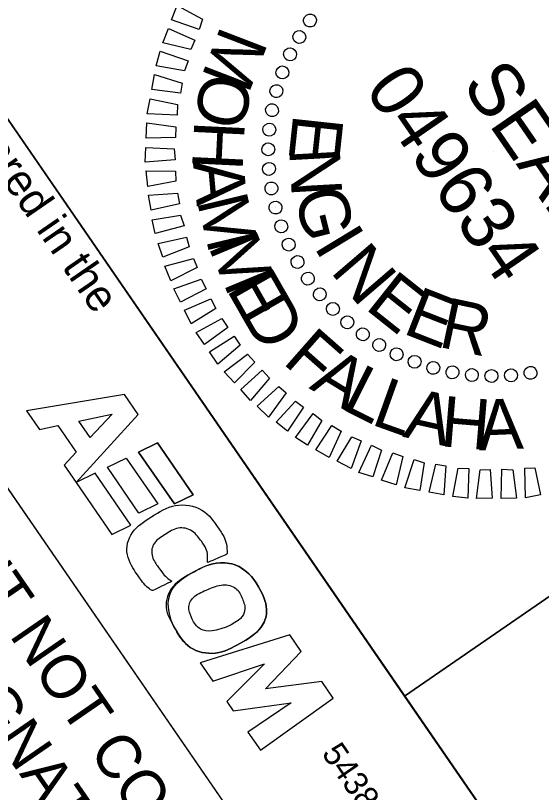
# Model space of a CAD drawing. Extents: x 2297526 to 2298642, y 599613 to 600819.
# Drawn here: x 2298486.8 to 2298526.4, y 599978.2 to 600036.6 of the extents above; entities that cross this region are included whole.
import ezdxf

# ---------------------------------------------------------------- set-up
doc = ezdxf.new("R2010")
doc.units = 0
for name, color, linetype in [('Default', 7, 'Continuous'), ('Exist DTM Drainline Cogo Elevation', 7, 'Continuous'), ('Exist Roads Curbs Cogo Comment', 7, 'Continuous'), ('Exist Roads EOP Cogo Elevation', 7, 'Continuous'), ('Exist Roads EOP Other Cogo Point CELL', 7, 'Continuous'), ('Exist Roads Soil Cogo Point CELL', 7, 'Continuous')]:
    doc.layers.add(name, color=color, linetype=linetype)

# ---------------------------------------------------------------- blocks, each defined once
blk = doc.blocks.new('block 3')
at = {"layer": 'Default'}
blk.add_open_spline([(0.122754, 0.093928), (0.12554, 0.09373), (0.127264, 0.091462), (0.126953, 0.088431), (0.126631, 0.085307), (0.12411, 0.082981), (0.121267, 0.083184), (0.118481, 0.083381), (0.116757, 0.085649), (0.117069, 0.088681), (0.11739, 0.091805), (0.119911, 0.094131), (0.122754, 0.093928)], degree=3, dxfattribs=at)
blk = doc.blocks.new('block 2')
at = {"layer": 'Default'}
for p, q in [((0.102337, 0.09375), (0.101973, 0.091327)), ((0.109658, 0.09375), (0.102337, 0.09375)), ((0.109295, 0.091327), (0.109658, 0.09375)), ((0.101973, 0.091327), (0.109295, 0.091327)), ((0.101374, 0.08733), (0.101738, 0.089754)), ((0.101738, 0.089754), (0.108181, 0.089754)), ((0.108181, 0.089754), (0.107817, 0.08733)), ((0.107817, 0.08733), (0.101374, 0.08733)), ((0.101138, 0.085757), (0.100775, 0.083333)), ((0.10846, 0.085757), (0.101138, 0.085757)), ((0.108096, 0.083333), (0.10846, 0.085757)), ((0.100775, 0.083333), (0.108096, 0.083333))]:
    blk.add_line(p, q, dxfattribs=at)
for points in [[(0.109295, 0.091327), (0.101973, 0.091327), (0.102337, 0.09375), (0.109658, 0.09375), (0.109295, 0.091327)], [(0.107817, 0.08733), (0.101374, 0.08733), (0.101738, 0.089754), (0.108181, 0.089754), (0.107817, 0.08733)], [(0.10846, 0.085757), (0.101138, 0.085757), (0.100775, 0.083333), (0.108096, 0.083333), (0.10846, 0.085757)]]:
    blk.add_lwpolyline(points, dxfattribs=at)
blk = doc.blocks.new('POINT_DISPLAY')
at = {"layer": 'Default'}
blk.add_line((0, 0), (0, 0), dxfattribs=at)

msp = doc.modelspace()

# ---------------------------------------------------------------- linework, layer by layer
at = {"layer": 'Exist DTM Drainline Cogo Elevation'}
for points in [[(2298537.65, 600073.144), (2298571.698, 600023.704), (2298516.106, 599985.419), (2298482.058, 600034.859)], [(2298571.698, 600023.704), (2298605.73, 599974.288), (2298550.137, 599936.003), (2298516.106, 599985.419)]]:
    msp.add_lwpolyline(points, close=True, dxfattribs=at)
at = {"layer": 'Exist Roads Curbs Cogo Comment'}
msp.add_line((2298469.087, 600025.926), (2298537.162, 599927.076), dxfattribs=at)
at = {"layer": 'Exist Roads EOP Cogo Elevation'}
for p, q in [((2298495.008, 600008.108), (2298487.648, 600006.895)), ((2298496.046, 600006.602), (2298495.008, 600008.108)), ((2298487.648, 600006.895), (2298488.611, 600005.496)), ((2298491.371, 600001.489), (2298496.046, 600006.602)), ((2298491.585, 600006.12), (2298494.069, 600006.641)), ((2298494.078, 600006.628), (2298492.431, 600004.891)), ((2298494.069, 600006.641), (2298494.078, 600006.628)), ((2298488.611, 600005.496), (2298490.007, 600005.789)), ((2298490.007, 600005.789), (2298491.385, 600003.787)), ((2298492.431, 600004.891), (2298491.585, 600006.12)), ((2298491.385, 600003.787), (2298490.46, 600002.811)), ((2298490.46, 600002.811), (2298491.371, 600001.489)), ((2298507.457, 599990.033), (2298500.707, 599987.932)), ((2298508.319, 599988.781), (2298507.457, 599990.033)), ((2298505.629, 599985.974), (2298508.319, 599988.781)), ((2298500.707, 599987.932), (2298501.659, 599986.55)), ((2298501.659, 599986.55), (2298505.561, 599987.852)), ((2298505.561, 599987.852), (2298502.713, 599985.019)), ((2298509.87, 599986.529), (2298505.629, 599985.974)), ((2298510.733, 599985.275), (2298509.87, 599986.529)), ((2298505.244, 599981.345), (2298510.733, 599985.275)), ((2298502.713, 599985.019), (2298503.198, 599984.315)), ((2298503.198, 599984.315), (2298507.573, 599984.927)), ((2298507.573, 599984.927), (2298504.307, 599982.706)), ((2298504.307, 599982.706), (2298505.244, 599981.345))]:
    msp.add_line(p, q, dxfattribs=at)
for points in [[(2298490.46, 600002.811), (2298491.371, 600001.489), (2298496.046, 600006.602), (2298495.008, 600008.108), (2298487.648, 600006.895), (2298488.611, 600005.496), (2298490.007, 600005.789), (2298491.385, 600003.787), (2298490.46, 600002.811)], [(2298505.244, 599981.345), (2298510.733, 599985.275), (2298509.87, 599986.529), (2298505.629, 599985.974), (2298508.319, 599988.781), (2298507.457, 599990.033), (2298500.707, 599987.932), (2298501.659, 599986.55), (2298505.561, 599987.852), (2298502.713, 599985.019), (2298503.198, 599984.315), (2298507.573, 599984.927), (2298504.307, 599982.706), (2298505.244, 599981.345)]]:
    msp.add_lwpolyline(points, dxfattribs=at)
for points in [[(2298498.586, 599994.064), (2298498.157, 599994.318), (2298497.746, 599994.855), (2298497.558, 599995.128), (2298496.952, 599996.007), (2298497.151, 599997.003), (2298498.063, 599997.588), (2298499.027, 599998.205), (2298500.192, 599997.958), (2298500.858, 599996.991), (2298501.173, 599996.534), (2298501.299, 599996.028), (2298501.243, 599995.457), (2298501.243, 599995.457), (2298502.758, 599996.106), (2298502.758, 599996.106), (2298502.703, 599996.882), (2298502.517, 599997.437), (2298502.119, 599998.016), (2298501.016, 599999.617), (2298498.773, 600000.019), (2298497.059, 599998.921), (2298495.397, 599997.856), (2298494.982, 599996.013), (2298496.063, 599994.443), (2298496.251, 599994.171), (2298496.686, 599993.6), (2298497.114, 599993.346), (2298497.114, 599993.346), (2298498.586, 599994.064), (2298498.586, 599994.064)], [(2298498.586, 599994.064), (2298498.157, 599994.318), (2298497.746, 599994.855), (2298497.558, 599995.128), (2298496.952, 599996.007), (2298497.151, 599997.003), (2298498.063, 599997.588), (2298499.027, 599998.205), (2298500.192, 599997.958), (2298500.858, 599996.991), (2298501.173, 599996.534), (2298501.299, 599996.028), (2298501.243, 599995.457), (2298501.243, 599995.457), (2298502.758, 599996.106), (2298502.758, 599996.106), (2298502.703, 599996.882), (2298502.517, 599997.437), (2298502.119, 599998.016), (2298501.016, 599999.617), (2298498.773, 600000.019), (2298497.059, 599998.921), (2298495.397, 599997.856), (2298494.982, 599996.013), (2298496.063, 599994.443), (2298496.251, 599994.171), (2298496.686, 599993.6), (2298497.114, 599993.346), (2298497.114, 599993.346), (2298498.586, 599994.064), (2298498.586, 599994.064)], [(2298498.528, 599991.147), (2298498.084, 599992.523), (2298498.718, 599993.941), (2298500.213, 599994.759), (2298501.998, 599995.736), (2298504.166, 599995.245), (2298505.103, 599993.653)], [(2298505.103, 599993.653), (2298506.022, 599992.093), (2298505.445, 599990.34), (2298503.713, 599989.392), (2298501.927, 599988.415), (2298499.759, 599988.906), (2298498.822, 599990.498), (2298498.697, 599990.711), (2298498.599, 599990.929), (2298498.528, 599991.147)], [(2298502.667, 599990.622), (2298503.746, 599991.067), (2298504.237, 599991.921), (2298503.892, 599992.731), (2298503.515, 599993.622), (2298502.428, 599993.92), (2298501.287, 599993.45), (2298500.208, 599993.005), (2298499.717, 599992.151), (2298500.06, 599991.341), (2298500.439, 599990.45), (2298501.526, 599990.152), (2298502.667, 599990.622)], [(2298502.667, 599990.622), (2298503.746, 599991.067), (2298504.237, 599991.921), (2298503.892, 599992.731), (2298503.515, 599993.622), (2298502.428, 599993.92), (2298501.287, 599993.45), (2298500.208, 599993.005), (2298499.717, 599992.151), (2298500.06, 599991.341), (2298500.439, 599990.45), (2298501.526, 599990.152), (2298502.667, 599990.622)]]:
    msp.add_open_spline(points, degree=3, dxfattribs=at)
at = {"layer": 'Exist Roads EOP Other Cogo Point CELL'}
msp.add_lwpolyline([(2298482.058, 600034.859), (2298550.12, 599936.028), (2298537.149, 599927.095), (2298469.087, 600025.926)], close=True, dxfattribs=at)
at = {"layer": 'Exist Roads Soil Cogo Point CELL'}
for points in [[(2298500.645, 600035.584), (2298498.546, 600036.311), (2298498.988, 600037.394), (2298500.886, 600036.365)], [(2298500.003, 600034.077), (2298497.888, 600034.588), (2298498.33, 600035.671), (2298500.3, 600034.774)], [(2298499.54, 600032.487), (2298497.399, 600032.857), (2298497.701, 600033.967), (2298499.8, 600033.24)], [(2298499.228, 600030.797), (2298497.07, 600031.073), (2298497.278, 600032.201), (2298499.367, 600031.548)], [(2298498.972, 600029.146), (2298496.732, 600029.243), (2298496.941, 600030.369), (2298498.997, 600029.941)], [(2298498.857, 600027.467), (2298496.639, 600027.415), (2298496.706, 600028.568), (2298498.882, 600028.264)], [(2298498.836, 600025.773), (2298496.572, 600025.607), (2298496.63, 600026.713), (2298498.748, 600026.613)], [(2298498.878, 600024.163), (2298496.768, 600023.775), (2298496.648, 600024.962), (2298498.849, 600024.92)], [(2298499.148, 600022.462), (2298497.02, 600021.981), (2298496.816, 600023.11), (2298499.004, 600023.265)], [(2298499.5, 600020.82), (2298497.328, 600020.226), (2298497.106, 600021.261), (2298499.236, 600021.621)], [(2298499.889, 600019.243), (2298497.898, 600018.445), (2298497.554, 600019.48), (2298499.682, 600019.961)], [(2298500.474, 600017.679), (2298498.495, 600016.684), (2298498.039, 600017.764), (2298500.211, 600018.358)], [(2298501.173, 600016.069), (2298499.241, 600015.066), (2298498.72, 600016.061), (2298500.796, 600016.794)], [(2298501.897, 600014.601), (2298500.033, 600013.44), (2298499.54, 600014.453), (2298501.522, 600015.327)], [(2298502.8, 600013.173), (2298501.031, 600011.873), (2298500.399, 600012.79), (2298502.34, 600013.841)], [(2298503.719, 600011.839), (2298502.046, 600010.399), (2298501.414, 600011.317), (2298503.259, 600012.505)], [(2298504.815, 600010.544), (2298503.292, 600009.004), (2298502.522, 600009.825), (2298504.272, 600011.153)], [(2298505.927, 600009.344), (2298504.502, 600007.665), (2298503.76, 600008.506), (2298505.385, 600009.953)], [(2298507.181, 600008.238), (2298505.85, 600006.421), (2298505.005, 600007.232), (2298506.639, 600008.727)], [(2298508.49, 600007.172), (2298507.281, 600005.357), (2298506.437, 600006.046), (2298507.892, 600007.622)], [(2298509.881, 600006.164), (2298508.785, 600004.302), (2298507.897, 600004.879), (2298509.227, 600006.697)], [(2298511.335, 600005.361), (2298510.41, 600003.372), (2298509.426, 600003.966), (2298510.635, 600005.781)], [(2298512.825, 600004.625), (2298512.08, 600002.554), (2298511.014, 600003.09), (2298512.128, 600004.924)], [(2298514.371, 600003.927), (2298513.708, 600001.914), (2298512.655, 600002.253), (2298513.617, 600004.31)], [(2298515.961, 600003.465), (2298515.469, 600001.323), (2298514.368, 600001.671), (2298515.208, 600003.724)], [(2298517.569, 600002.974), (2298517.236, 600000.9), (2298516.108, 600001.107), (2298516.817, 600003.235)], [(2298519.203, 600002.746), (2298519.067, 600000.563), (2298517.94, 600000.77), (2298518.451, 600002.884)], [(2298520.937, 600002.547), (2298520.868, 600000.327), (2298519.724, 600000.441), (2298520.142, 600002.573)], [(2298522.548, 600002.469), (2298522.684, 600000.308), (2298521.515, 600000.281), (2298521.791, 600002.439)], [(2298524.245, 600002.447), (2298524.529, 600000.307), (2298523.36, 600000.281), (2298523.429, 600002.5)], [(2298525.899, 600002.604), (2298526.323, 600000.559), (2298525.194, 600000.354), (2298525.141, 600002.573)]]:
    msp.add_lwpolyline(points, close=True, dxfattribs=at)
for centre, major_axis in [((2298508.977, 600036.259), (-0.396, 0.282)), ((2298508.173, 600035.02), (-0.419, 0.246)), ((2298507.481, 600033.715), (-0.439, 0.209)), ((2298506.905, 600032.354), (-0.455, 0.17)), ((2298506.45, 600030.949), (-0.469, 0.129)), ((2298506.119, 600029.51), (-0.478, 0.088)), ((2298505.915, 600028.047), (-0.484, 0.046)), ((2298505.839, 600026.571), (-0.486, 0.004)), ((2298505.892, 600025.095), (-0.485, -0.039)), ((2298506.073, 600023.629), (-0.479, -0.081)), ((2298506.382, 600022.185), (-0.47, -0.122)), ((2298506.815, 600020.772), (-0.458, -0.163)), ((2298507.37, 600019.403), (-0.442, -0.202)), ((2298508.042, 600018.088), (-0.423, -0.24)), ((2298508.826, 600016.836), (-0.4, -0.276)), ((2298509.716, 600015.657), (-0.375, -0.31)), ((2298510.705, 600014.56), (-0.346, -0.341)), ((2298511.786, 600013.554), (-0.315, -0.37)), ((2298512.951, 600012.646), (-0.282, -0.396)), ((2298514.191, 600011.842), (-0.246, -0.419)), ((2298515.496, 600011.15), (-0.209, -0.439)), ((2298516.856, 600010.574), (-0.17, -0.455)), ((2298518.261, 600010.119), (-0.129, -0.469)), ((2298519.701, 600009.788), (-0.088, -0.478)), ((2298525.581, 600009.742), (0.081, -0.479)), ((2298521.164, 600009.584), (-0.046, -0.484)), ((2298522.639, 600009.508), (-0.004, -0.486)), ((2298524.115, 600009.561), (0.039, -0.485))]:
    msp.add_ellipse(centre, major_axis=major_axis, ratio=0.999708, dxfattribs=at)

# ---------------------------------------------------------------- block references
at = {"layer": 'Exist Roads EOP Cogo Elevation', "xscale": 648.0018668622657, "yscale": 648.0018668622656, "rotation": -55.44594090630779}
for name in ['block 2', 'block 3']:
    msp.add_blockref(name, (2298409.858, 600024.644), dxfattribs=at)
at = {"layer": 'Exist Roads Soil Cogo Point CELL', "xscale": 41.411959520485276, "yscale": 41.41195952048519, "rotation": -55.44551104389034}
for p in [(2298508.949, 600036.262), (2298506.891, 600032.345), (2298506.416, 600030.952), (2298506.102, 600029.506), (2298505.881, 600028.041), (2298505.827, 600026.57), (2298522.769, 600026.433), (2298505.869, 600025.083), (2298506.06, 600023.616), (2298506.353, 600022.178), (2298506.796, 600020.761), (2298507.368, 600019.394), (2298508.025, 600018.084), (2298508.812, 600016.822), (2298509.71, 600015.637), (2298510.7, 600014.556), (2298511.774, 600013.533), (2298512.939, 600012.614), (2298514.178, 600011.828), (2298515.48, 600011.127), (2298516.856, 600010.557), (2298518.249, 600010.082), (2298519.696, 600009.767), (2298525.586, 600009.724), (2298521.159, 600009.545), (2298522.63, 600009.492), (2298524.118, 600009.533)]:
    msp.add_blockref('POINT_DISPLAY', p, dxfattribs=at)

# ---------------------------------------------------------------- texts
at = {"layer": 'Exist Roads Curbs Cogo Comment'}
for s, p in [('DOCUMENT NOT CONSIDERED FINAL', (2298471.145, 600011.993)), ('UNLESS ALL SIGNATURES COMPLETED', (2298465.071, 600011.505))]:
    msp.add_text(s, height=3.30002, rotation=304.55406, dxfattribs=at).set_placement(p)
at = {"layer": 'Exist Roads EOP Cogo Elevation'}
for s, height, p in [('Prepared in the ', 2.40001, (2298480.342, 600032.132)), ('5438 Wade Park Boulevard, Suite 200', 1.80001, (2298509.809, 599981.109))]:
    msp.add_text(s, height=height, rotation=304.55406, dxfattribs=at).set_placement(p)
at = {"layer": 'Exist Roads Soil Cogo Point CELL'}
for s, height, rotation, p in [('M', 3.807, 248.96518, (2298502.302, 600035.975)), ('SEAL', 4.0496, 304.55449, (2298520.351, 600031.432)), ('049634', 4.0508, 304.55449, (2298513.025, 600031.118)), ('O', 3.807, 258.06127, (2298501.004, 600032.516)), ('H', 3.807, 267.21962, (2298500.275, 600028.768)), ('E', 3.807, 263.83138, (2298507.734, 600029.281)), ('N', 3.807, 273.18844, (2298507.41, 600026.591)), ('A', 3.807, 275.10364, (2298500.159, 600025.636)), ('G', 3.807, 284.0577, (2298507.769, 600023.232)), ('M', 3.807, 283.4799, (2298500.445, 600022.716)), ('I', 3.807, 301.25569, (2298509.217, 600019.267)), ('M', 3.807, 292.57088, (2298501.296, 600019.266)), ('N', 3.807, 310.61088, (2298510.443, 600017.367)), ('E', 3.807, 299.69755, (2298502.653, 600016.045)), ('E', 3.807, 321.52135, (2298513.041, 600014.62)), ('E', 3.807, 338.67858, (2298515.873, 600012.753)), ('D', 3.807, 299.69755, (2298503.647, 600014.313)), ('R', 3.807, 348.0359, (2298518.558, 600011.724)), ('F', 3.807, 318.63726, (2298506.836, 600010.521)), ('A', 3.807, 328.53791, (2298508.854, 600008.608)), ('L', 3.807, 333.28279, (2298511.234, 600007.088)), ('L', 3.807, 340.24804, (2298513.489, 600005.898)), ('A', 3.807, 347.43332, (2298515.904, 600004.95)), ('H', 3.807, 355.23759, (2298518.721, 600004.232)), ('A', 3.807, 2.43277, (2298521.699, 600003.908))]:
    msp.add_text(s, height=height, rotation=rotation, dxfattribs=at).set_placement(p)

doc.saveas('drawing.dxf')
